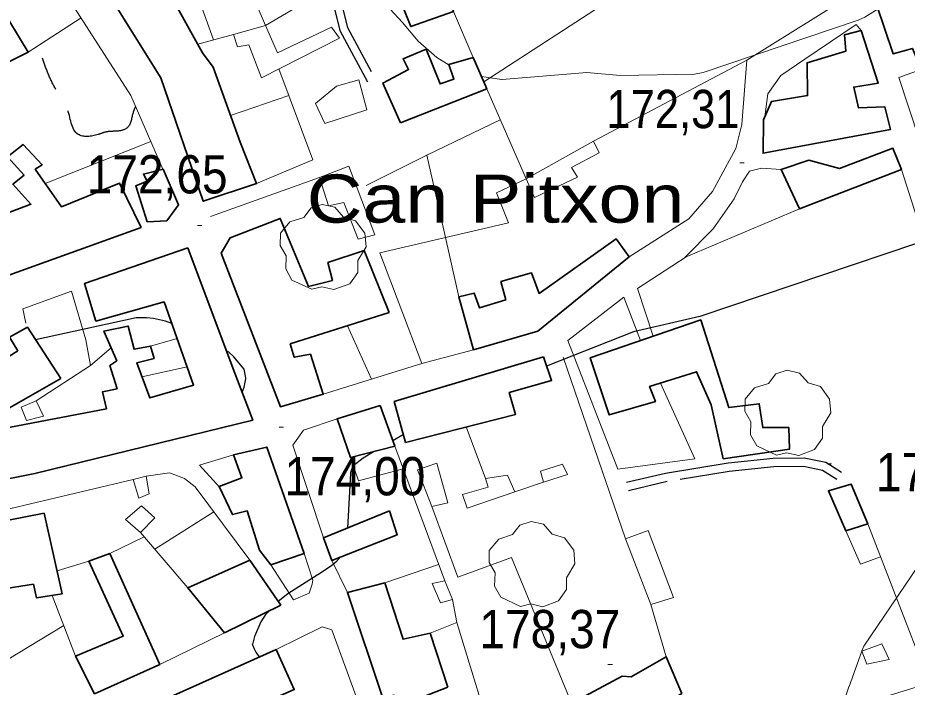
# Model space of a CAD drawing. Extents: x 480269 to 484877, y 4383588 to 4386804.
# Drawn here: x 480607.5 to 480810.8, y 4385217.3 to 4385370.4 of the extents above; entities that cross this region are included whole.
import ezdxf

# ---------------------------------------------------------------- set-up
doc = ezdxf.new("R2010")
doc.units = 0
doc.header["$LTSCALE"] = 3.8
doc.linetypes.add('LONG_DASHED', pattern=[7.5, 6, -1.5])
doc.linetypes.add('MEDIUM_DASHED', pattern=[4.5, 3, -1.5])
for name, color, linetype, lineweight in [('29', 7, 'Continuous', 13), ('38', 7, 'Continuous', 25), ('47', 7, 'Continuous', 35), ('51', 7, 'Continuous', 13), ('7', 7, 'Continuous', 13), ('8', 7, 'Continuous', 25), ('9', 7, 'Continuous', 13)]:
    doc.layers.add(name, color=color, linetype=linetype, lineweight=lineweight)
doc.layers.add('5', color=7, linetype='Continuous')

msp = doc.modelspace()

# ---------------------------------------------------------------- linework, layer by layer
at = {"layer": '29'}
for points in [[(480674.67, 4385308.3), (480670.13, 4385310.42), (480668.72, 4385312.96), (480668.82, 4385315.94), (480667.45, 4385318.35), (480667.49, 4385321.1), (480669.65, 4385323.7), (480672.84, 4385324.7), (480674.49, 4385326.89), (480677.06, 4385327.72), (480679.92, 4385327.07), (480681.87, 4385324.8), (480684.68, 4385323.98), (480686.81, 4385321.13), (480687.05, 4385318), (480685.17, 4385314.85), (480685.17, 4385312.17), (480683.35, 4385309.56), (480679.73, 4385308.22), (480676.96, 4385308.85)], [(480780.89, 4385270.39), (480776.35, 4385272.51), (480774.94, 4385275.05), (480775.04, 4385278.03), (480773.67, 4385280.44), (480773.71, 4385283.19), (480775.87, 4385285.79), (480779.06, 4385286.79), (480780.71, 4385288.98), (480783.28, 4385289.81), (480786.14, 4385289.16), (480788.09, 4385286.89), (480790.9, 4385286.07), (480793.03, 4385283.22), (480793.27, 4385280.09), (480791.39, 4385276.94), (480791.39, 4385274.26), (480789.57, 4385271.65), (480785.95, 4385270.31), (480783.18, 4385270.94)], [(480722.4, 4385235.81), (480717.86, 4385237.93), (480716.45, 4385240.47), (480716.55, 4385243.45), (480715.18, 4385245.86), (480715.22, 4385248.61), (480717.38, 4385251.21), (480720.57, 4385252.21), (480722.22, 4385254.4), (480724.79, 4385255.23), (480727.65, 4385254.58), (480729.6, 4385252.31), (480732.41, 4385251.49), (480734.54, 4385248.64), (480734.78, 4385245.51), (480732.9, 4385242.36), (480732.9, 4385239.68), (480731.08, 4385237.07), (480727.46, 4385235.73), (480724.69, 4385236.36)]]:
    msp.add_lwpolyline(points, close=True, dxfattribs=at)
at = {"layer": '38'}
for points in [[(480680.09, 4385384.03), (480679.92, 4385377.39), (480679.81, 4385372.4), (480681.09, 4385367.46), (480687.36, 4385355.7)], [(480795.72, 4385266.43), (480792.13, 4385268.69), (480787.22, 4385269.73), (480780.12, 4385269.62), (480769.82, 4385268.58), (480755.51, 4385266.22), (480746.59, 4385264.12)]]:
    msp.add_lwpolyline(points, dxfattribs=at)
at = {"layer": '38', "linetype": 'MEDIUM_DASHED'}
for points in [[(480681.96, 4385383.98), (480681.79, 4385377.35), (480681.68, 4385372.62), (480682.85, 4385368.14), (480689.01, 4385356.58)], [(480794.69, 4385264.8), (480791.4, 4385266.88), (480787.03, 4385267.81), (480780.24, 4385267.7), (480770.07, 4385266.67), (480755.89, 4385264.33), (480747.03, 4385262.25)]]:
    msp.add_lwpolyline(points, dxfattribs=at)
at = {"layer": '38', "linetype": 'LONG_DASHED'}
msp.add_spline([(480634.32, 4385350.04), (480633.8, 4385348.67), (480632.6, 4385345.36), (480630.23, 4385344.46), (480627.8, 4385344.31), (480625.84, 4385343.69), (480621.26, 4385343.71), (480618.73, 4385349.73), (480616.16, 4385354.05), (480614.44, 4385357.47), (480613.07, 4385361.15)], degree=3, dxfattribs=at)
at = {"layer": '47'}
for points in [[(480623.58, 4385383.14), (480640.53, 4385393.95), (480643.34, 4385390.02), (480636.64, 4385385.89), (480649.71, 4385362.36), (480652.14, 4385359.07), (480658.29, 4385341.91), (480662.03, 4385332.48), (480649.85, 4385328.43), (480640.14, 4385356.67)], [(480707.07, 4385371.84), (480705.48, 4385376.19), (480695.54, 4385372.71), (480697.28, 4385368.36)], [(480812.6, 4385376.03), (480817.16, 4385361.89), (480813.11, 4385360.62), (480811.95, 4385363.37), (480807.51, 4385362.13), (480803.74, 4385373.4)], [(480609.81, 4385362.48), (480604.34, 4385359.74), (480600.69, 4385366.99), (480601.17, 4385368.49), (480602.46, 4385369.51), (480604.05, 4385370.17), (480605.4, 4385369.79)], [(480806.94, 4385344.85), (480805.62, 4385350.05), (480799.63, 4385349.77), (480798.53, 4385354.51), (480804.13, 4385355.44), (480800.22, 4385367.46), (480796.43, 4385366.48), (480796.76, 4385362.76), (480787.88, 4385360.11), (480788, 4385352.57), (480779.73, 4385351.27), (480777.89, 4385347.07), (480777.8, 4385339.42)], [(480694.96, 4385346.34), (480690.87, 4385355.45), (480696.78, 4385358.51), (480695.51, 4385361.02), (480700.81, 4385363.19), (480703.98, 4385355.24), (480707.15, 4385356.34), (480706.01, 4385359.66), (480711.55, 4385361.28), (480714.66, 4385354.11)], [(480635.63, 4385322.4), (480630.73, 4385332.55), (480617.45, 4385327.13), (480611.43, 4385335.74), (480613.03, 4385336.77), (480608.71, 4385341.39), (480605.12, 4385338.62), (480608.91, 4385334.42), (480606.29, 4385332.3), (480610.45, 4385327.73), (480598.81, 4385323.35), (480603.49, 4385310.84)], [(480809.45, 4385335.7), (480807.5, 4385340.56), (480795.24, 4385335.9), (480788.25, 4385337.81), (480781.94, 4385335.72), (480786.15, 4385326.68)], [(480637.04, 4385323.73), (480641.52, 4385323.92), (480644.18, 4385327.62), (480640.67, 4385335.76), (480636.17, 4385334.65), (480637.06, 4385333.01), (480634.43, 4385331.95)], [(480692.33, 4385302.97), (480686.62, 4385317.19), (480678.35, 4385314.46), (480679.37, 4385310.33), (480673.92, 4385308.96), (480667.45, 4385324.52), (480656.02, 4385320.07), (480653.95, 4385316.57), (480667.48, 4385281.45), (480677.26, 4385284.32), (480674.34, 4385293.46), (480670.64, 4385292.78), (480669.75, 4385295.82)], [(480747.22, 4385315.76), (480744.23, 4385319.82), (480726.61, 4385307.37), (480724.89, 4385312.04), (480717.89, 4385310.08), (480719, 4385305.87), (480712.99, 4385304.05), (480711.8, 4385307.42), (480708.24, 4385306.57), (480711.65, 4385294.49), (480726.3, 4385298.73)], [(480646.29, 4385317.78), (480622.71, 4385309.63), (480625.31, 4385301.05), (480640.89, 4385305.41), (480647.63, 4385286.39), (480637.62, 4385283.46), (480634.64, 4385291.47), (480638.62, 4385292.5), (480637.79, 4385295.33), (480634.02, 4385294.6), (480632.65, 4385299.89), (480627.16, 4385298.73), (480630.09, 4385291.95), (480628.49, 4385290.87), (480630.16, 4385285.51), (480626.8, 4385284.85), (480627.73, 4385280.94), (480595.33, 4385274.77), (480583.1, 4385269.14), (480584.78, 4385260.87), (480611.37, 4385266.18), (480661.18, 4385278.38), (480656.67, 4385290.13)], [(480768.66, 4385269.58), (480765.95, 4385281.88), (480762.61, 4385289.44), (480751.86, 4385286.09), (480753.21, 4385282.63), (480742.65, 4385279.59), (480738.3, 4385292.67), (480763.58, 4385301.32), (480769.95, 4385281.27), (480776.95, 4385282.14), (480777.74, 4385276.67), (480783.73, 4385276.68), (480783.82, 4385271.75)], [(480617.27, 4385287.91), (480609.64, 4385299.64), (480605.53, 4385297.34), (480607.43, 4385294.26), (480595.06, 4385286.46), (480600.12, 4385278.16)], [(480727.6, 4385292.85), (480729.45, 4385287.46), (480719.78, 4385284.71), (480721.25, 4385279.71), (480696.11, 4385273.31), (480693.49, 4385282.65)], [(480690.29, 4385281.75), (480693.6, 4385272.42), (480683.54, 4385269.84), (480680.46, 4385278.7)], [(480672.9, 4385247.92), (480665.32, 4385245.34), (480662.73, 4385248.68), (480659.86, 4385257.63), (480656.55, 4385256.79), (480653.5, 4385263.25), (480658.7, 4385265.21), (480656.76, 4385270.44), (480664.35, 4385272.24)], [(480801.75, 4385254.67), (480796.73, 4385253.05), (480792.74, 4385262.23), (480797.98, 4385263.76)], [(480613.46, 4385257.14), (480601.4, 4385254.77), (480600.7, 4385257), (480586.44, 4385253.4), (480593.23, 4385243.13), (480601.94, 4385244.79), (480603.25, 4385239.68), (480611.03, 4385240.88), (480611.7, 4385237.78), (480617.58, 4385238.68)], [(480692.4, 4385257.66), (480694.2, 4385252.18), (480679.22, 4385246.32), (480677.33, 4385251.45)], [(480628.51, 4385247.9), (480623.71, 4385246.16), (480631.54, 4385228.97), (480620.66, 4385224.43), (480625.01, 4385215.84), (480639.91, 4385222.55)], [(480667.55, 4385236.07), (480654.74, 4385229.79), (480646.36, 4385240.06), (480660.52, 4385246.35)], [(480705.79, 4385217.36), (480701.73, 4385229.68), (480695.54, 4385228.3), (480691.37, 4385241.17), (480682.79, 4385239.02), (480690.97, 4385214.57), (480693.41, 4385215.52), (480694.38, 4385212.92)], [(480644.36, 4385205.21), (480640.18, 4385214.11), (480666.49, 4385225.94), (480670.65, 4385216.8)], [(480759.24, 4385215.92), (480755.69, 4385224.29), (480747.63, 4385219.73), (480745.57, 4385219.83), (480729.5, 4385211.23), (480727.79, 4385214.12), (480717.67, 4385208.16), (480715.53, 4385212.43), (480713.73, 4385211.52), (480706.51, 4385211.35), (480706.48, 4385204.17), (480712.6, 4385204.16), (480715.29, 4385206.55), (480718.61, 4385201.57), (480713.33, 4385198.99), (480715.08, 4385196.38), (480700.36, 4385188.31), (480703.16, 4385183.27), (480741.37, 4385204.94)]]:
    msp.add_lwpolyline(points, close=True, dxfattribs=at)
at = {"layer": '47', "lineweight": 13}
for points in [[(480664.08, 4385368.59), (480661.97, 4385373.55), (480675.83, 4385380.85), (480677.91, 4385376.85)], [(480680.97, 4385365.72), (480679.15, 4385368.22), (480666.79, 4385362.34), (480664.08, 4385368.59), (480656.74, 4385366.52), (480657.67, 4385363.73), (480660.24, 4385364.22), (480663.15, 4385356.64)], [(480687.21, 4385349.34), (480677.65, 4385346.24), (480675.52, 4385350.78), (480680.31, 4385354.76), (480685.41, 4385356.21)], [(480739.02, 4385342.14), (480740.35, 4385339.47), (480734.03, 4385336.16), (480735.42, 4385333.92), (480725.55, 4385329.27), (480723.64, 4385333.56)], [(480683.11, 4385336.47), (480689.1, 4385320.78), (480685.23, 4385319.78), (480682, 4385328.12), (480678.5, 4385327.41), (480676.43, 4385333.85)], [(480613.36, 4385279.26), (480609.48, 4385278.31), (480608.21, 4385281.33), (480611.68, 4385282.77)], [(480705.79, 4385259.51), (480702.13, 4385258.67), (480698.84, 4385267.03), (480703.21, 4385268.55)], [(480727.65, 4385264.2), (480726.93, 4385266.71), (480731.93, 4385268.35), (480733.07, 4385265.95)], [(480637.5, 4385261.55), (480635.15, 4385260.57), (480633.83, 4385264.83), (480636.79, 4385265.56)], [(480710.2, 4385258.23), (480709.12, 4385261.36), (480714.94, 4385263.07), (480714.35, 4385265.03), (480719.37, 4385265.84), (480721.08, 4385261.97)], [(480635.47, 4385252.73), (480632.1, 4385255.67), (480635.72, 4385258.78), (480638.8, 4385256.08)], [(480757.35, 4385237.81), (480752.15, 4385236.21), (480746.38, 4385251.26), (480751.56, 4385253.15)], [(480706.81, 4385237.36), (480704.07, 4385236.61), (480702.16, 4385241.04), (480705.03, 4385241.62)], [(480801.55, 4385222.61), (480800.38, 4385225.61), (480804.94, 4385227.24), (480806.65, 4385223.66)]]:
    msp.add_lwpolyline(points, close=True, dxfattribs=at)
at = {"layer": '51'}
for p, q in [((480713.96, 4385355.73), (480786.79, 4385403.01)), ((480643.34, 4385390.02), (480652.22, 4385365.3)), ((480609.81, 4385362.48), (480621.96, 4385370.36)), ((480707.07, 4385371.84), (480711.55, 4385361.28)), ((480656.74, 4385366.52), (480648.63, 4385364.31)), ((480774.11, 4385360.7), (480739.02, 4385342.14)), ((480669.43, 4385352.58), (480656.11, 4385348)), ((480700.97, 4385338.99), (480717.75, 4385347.05)), ((480613.69, 4385332.52), (480637.89, 4385342.11)), ((480651.5, 4385324.95), (480676.43, 4385333.85)), ((480688.33, 4385287.78), (480682.83, 4385299.96)), ((480643.87, 4385297.02), (480637.79, 4385295.33)), ((480624.11, 4385290.87), (480628.81, 4385294.92)), ((480699.8, 4385291.36), (480677.26, 4385284.32)), ((480746.38, 4385251.26), (480732.11, 4385292.81)), ((480635.84, 4385288.26), (480646.14, 4385290.61)), ((480714.35, 4385265.03), (480709.92, 4385276.83)), ((480693.6, 4385272.42), (480705.03, 4385241.62)), ((480600.7, 4385257), (480633.83, 4385264.83)), ((480727.65, 4385264.2), (480721.08, 4385261.97)), ((480652.27, 4385257.4), (480638.8, 4385248.86)), ((480801.75, 4385254.67), (480815.78, 4385218.3)), ((480646.36, 4385240.06), (480635.47, 4385252.73)), ((480636.34, 4385251.73), (480628.51, 4385247.9)), ((480623.71, 4385246.16), (480616.42, 4385243.93)), ((480682.79, 4385239.02), (480679.22, 4385246.32)), ((480691.37, 4385241.17), (480703.63, 4385245.41)), ((480620.66, 4385224.43), (480615.29, 4385238.33)), ((480706.81, 4385237.36), (480707.81, 4385232.14)), ((480755.69, 4385224.29), (480752.15, 4385236.21)), ((480654.99, 4385229.92), (480639.91, 4385222.55))]:
    msp.add_line(p, q, dxfattribs=at)
for points in [[(480773.99, 4385444.37), (480795.71, 4385374.17), (480774.11, 4385360.7), (480772.92, 4385345.98), (480771.56, 4385340.49), (480766.27, 4385330.69), (480760.81, 4385324.4), (480747.22, 4385315.76)], [(480640.64, 4385335.76), (480633.33, 4385352.59), (480615.65, 4385380.21)], [(480813.5, 4385342.6), (480808.81, 4385356.71), (480843.18, 4385369.07), (480840.18, 4385378.34)], [(480778.19, 4385347.75), (480778.89, 4385353), (480781.86, 4385357.19), (480787.32, 4385360.92), (480799.05, 4385368.85), (480800.2, 4385367.46)], [(480667.16, 4385358.69), (480674.88, 4385337.87), (480662.03, 4385332.48)], [(480714.66, 4385354.11), (480723.64, 4385333.56), (480716.85, 4385330.36), (480719.59, 4385323.51), (480690.18, 4385316.64), (480699.8, 4385291.36), (480711.65, 4385294.49)], [(480708.24, 4385306.57), (480705.22, 4385320.16), (480700.97, 4385338.99), (480687.12, 4385332.01)], [(480781.94, 4385335.72), (480777.46, 4385336.03), (480774.74, 4385335.27), (480773.08, 4385332.89), (480771.19, 4385328.95), (480766.42, 4385322.14), (480759.83, 4385315.52)], [(480764.18, 4385202.37), (480844.08, 4385227.03), (480809.45, 4385335.7)], [(480786.15, 4385326.68), (480760.21, 4385315.76), (480749.09, 4385308.47), (480752.7, 4385297.6)], [(480609.31, 4385300.56), (480608.6, 4385303.83), (480619.77, 4385307.86), (480623.01, 4385296.77), (480624.11, 4385290.87), (480611.68, 4385282.77)], [(480749.77, 4385296.59), (480745.99, 4385306.5), (480733.15, 4385296.57), (480744.58, 4385267.17), (480762.24, 4385269.58), (480754.34, 4385286.87)], [(480677.33, 4385251.45), (480670.29, 4385272.66), (480672.75, 4385276.06), (480680.46, 4385278.7)], [(480656.76, 4385270.44), (480648.96, 4385268.08), (480653.64, 4385262.98)], [(480695.51, 4385267.27), (480685.3, 4385264.54), (480683.54, 4385269.84)], [(480636.79, 4385265.56), (480642.15, 4385266.36), (480645.57, 4385265.03), (480647.99, 4385263.12), (480660.52, 4385246.35)], [(480702.13, 4385258.67), (480708.03, 4385242.47), (480720.3, 4385247), (480734.05, 4385213.67)], [(480804.65, 4385247.17), (480800.04, 4385245.46), (480796.73, 4385253.05)], [(480665.32, 4385245.34), (480670.48, 4385237.29), (480674.03, 4385238.83), (480674.77, 4385240.88), (480674.92, 4385241.82), (480672.9, 4385247.92)], [(480617.96, 4385231.45), (480605.06, 4385223.62), (480593.23, 4385243.13)], [(480714.09, 4385211.71), (480707.81, 4385232.14), (480701.73, 4385229.68)], [(480666.49, 4385225.94), (480677.04, 4385231.13), (480679.25, 4385230.43), (480688.63, 4385204.81), (480676.83, 4385201.29)]]:
    msp.add_lwpolyline(points, dxfattribs=at)
at = {"layer": '7'}
for p, q in [((480772.46, 4385337.22), (480773.46, 4385337.22)), ((480648.54, 4385322.9), (480649.54, 4385322.9)), ((480667.17, 4385276.8), (480668.17, 4385276.8)), ((480792.44, 4385268.43), (480793.44, 4385268.43)), ((480742.36, 4385222.52), (480743.36, 4385222.52))]:
    msp.add_line(p, q, dxfattribs=at)
at = {"layer": '8'}
msp.add_line((480695.6, 4385275.11), (480693.15, 4385273.68), dxfattribs=at)
for points in [[(480840.68, 4385328.18), (480763.39, 4385302.05), (480748.16, 4385298.6), (480728.33, 4385290.73)], [(480642.63, 4385300.49), (480641.21, 4385301.05), (480638.45, 4385301.65), (480636.9, 4385301.79), (480634.53, 4385301.79), (480611.52, 4385296.75)], [(480658.76, 4385284.69), (480659.2, 4385285.89), (480659.57, 4385287.86), (480659.56, 4385288.05), (480659.2, 4385290.07), (480656.87, 4385292.83), (480655.66, 4385293.94), (480655.13, 4385294.24)], [(480688.93, 4385271.22), (480686.37, 4385269.73), (480684.05, 4385267.86), (480683.97, 4385267.73), (480683.7, 4385267.05), (480683.52, 4385266.41), (480683.49, 4385266.23), (480682.81, 4385253.71)], [(480681, 4385247.02), (480680.88, 4385246.79), (480680.76, 4385246.62), (480680.16, 4385245.94), (480679.19, 4385245.1), (480676.05, 4385243.03), (480676.01, 4385243.02), (480675.86, 4385242.95), (480669.16, 4385238.72), (480666.98, 4385236.9)], [(480664.87, 4385234.76), (480664.4, 4385234.23), (480664.29, 4385234.23), (480664.27, 4385234.23), (480664.25, 4385234.22), (480663.02, 4385232.28), (480661.58, 4385228.96), (480661.19, 4385227.42), (480661.1, 4385227.22), (480661.05, 4385227.16), (480661.04, 4385227.15), (480661.04, 4385227.13), (480661.07, 4385227.09), (480661.12, 4385227.05), (480661.13, 4385227.04), (480661.48, 4385226.09), (480661.85, 4385225.34), (480662.14, 4385224.9), (480662.71, 4385224.24)]]:
    msp.add_lwpolyline(points, dxfattribs=at)
at = {"layer": '9'}
for points in [[(480698.98, 4385365.05), (480695.39, 4385369.26), (480692.54, 4385372.35), (480686.99, 4385376.55), (480683.42, 4385379.8), (480682.3, 4385381.29), (480676.95, 4385390.67), (480676.43, 4385391.6)], [(480804.08, 4385372.4), (480801.06, 4385370.5), (480799.56, 4385369.79), (480764.08, 4385357.9), (480762.17, 4385357.5), (480745.13, 4385357.15), (480737.5, 4385357.89), (480718.14, 4385356.26), (480718.13, 4385356.26), (480713.44, 4385356.92)], [(480706.05, 4385359.54), (480703.21, 4385361.28), (480698.98, 4385365.05)], [(480849.84, 4385279.84), (480843.92, 4385274.53), (480843.92, 4385274.51), (480843.91, 4385274.5), (480843.87, 4385274.47), (480839.73, 4385267.09), (480839.05, 4385264.78), (480838.97, 4385264.18), (480839.09, 4385260.57), (480838.79, 4385259.07), (480838.41, 4385258.27), (480838.12, 4385257.81), (480837.93, 4385257.6), (480837.52, 4385257.3), (480836.12, 4385256.74), (480827.08, 4385254.5), (480825.9, 4385254.04), (480817.2, 4385249.08), (480815.92, 4385247.97), (480813.35, 4385245.13), (480800.87, 4385226.7), (480800.61, 4385226.17), (480800.4, 4385225.62)], [(480800.39, 4385225.58), (480797.45, 4385217.48), (480797.44, 4385217.47), (480797.43, 4385217.45), (480795.26, 4385211.08), (480794.91, 4385208.8), (480794.93, 4385206.06), (480796.94, 4385198.22), (480799.87, 4385191.28), (480801.92, 4385188.43), (480801.95, 4385188.41), (480802, 4385188.38), (480802.1, 4385188.28), (480802.87, 4385187.36), (480803.87, 4385185.87), (480804.03, 4385185.71), (480804.19, 4385185.48), (480804.86, 4385183.83)]]:
    msp.add_lwpolyline(points, dxfattribs=at)

# ---------------------------------------------------------------- texts
at = {"layer": '5', "width": 1.2}
msp.add_text('Can Pitxon', height=11, dxfattribs=at).set_placement((480673.49, 4385323.54))
at = {"layer": '7'}
for s, width, p in [('172,31', 0.85, (480742, 4385345.14)), ('172,65', 0.9, (480623.2, 4385330.21)), ('178,68', 0.9, (480803.59, 4385262.14)), ('174,00', 0.9, (480668.4, 4385261.2)), ('178,37', 0.9, (480712.96, 4385226.25))]:
    msp.add_text(s, height=8.75, dxfattribs=dict(at, width=width)).set_placement(p)

doc.saveas('drawing.dxf')
